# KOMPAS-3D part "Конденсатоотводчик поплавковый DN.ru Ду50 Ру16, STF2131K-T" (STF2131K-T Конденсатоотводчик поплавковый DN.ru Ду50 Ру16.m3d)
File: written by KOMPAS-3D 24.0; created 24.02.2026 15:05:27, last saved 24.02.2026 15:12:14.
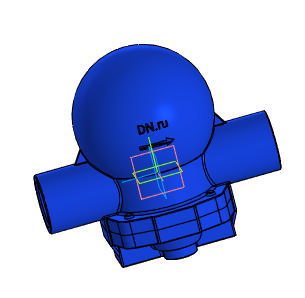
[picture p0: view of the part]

Document properties: Автор: R2D2; Полное имя файла: STF2131K-T Конденсатоотводчик поплавковый DN.ru Ду50 Ру16.cdw

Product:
- Part/product: Конденсатоотводчик поплавковый DN.ru Ду50 Ру16  | designation STF2131K-T
    Масса: 15.5
    Раздел спецификации: Прочие изделия
    Форматы листов документа: A2
    Примечание: D150-00323
    additional columns: D150-00323

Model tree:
1. Операция без истории:2

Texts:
  STF2131K-T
